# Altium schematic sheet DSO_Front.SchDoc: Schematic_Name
size A4; CompanyName: University of Melbourne; Engineer: Your Name Here; DocumentNumber: 1; Revision: 0.1; SheetNumber: 1; SheetTotal: 1; Title_Project: Project_Title; StudentNo: Student No.
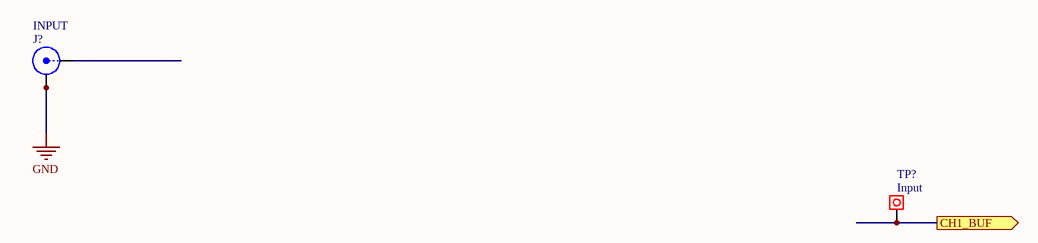
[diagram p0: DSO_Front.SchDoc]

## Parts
J?  INPUT  [BNC_VERT]
TP?  INPUT  [Testpoin]

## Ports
CH1_BUF (out)

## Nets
GND: J?.2(Y) J?.3(Y) J?.4(Y) J?.5(Y)
CH1_BUF: TP?.1 ; port CH1_BUF

Not connected (* = marked no-connect by the designer): J? 1(X)

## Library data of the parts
J? = BNC: BNC Straight; Reviewed by: RM - 2018/08/05
TP? = Test Point: Pad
